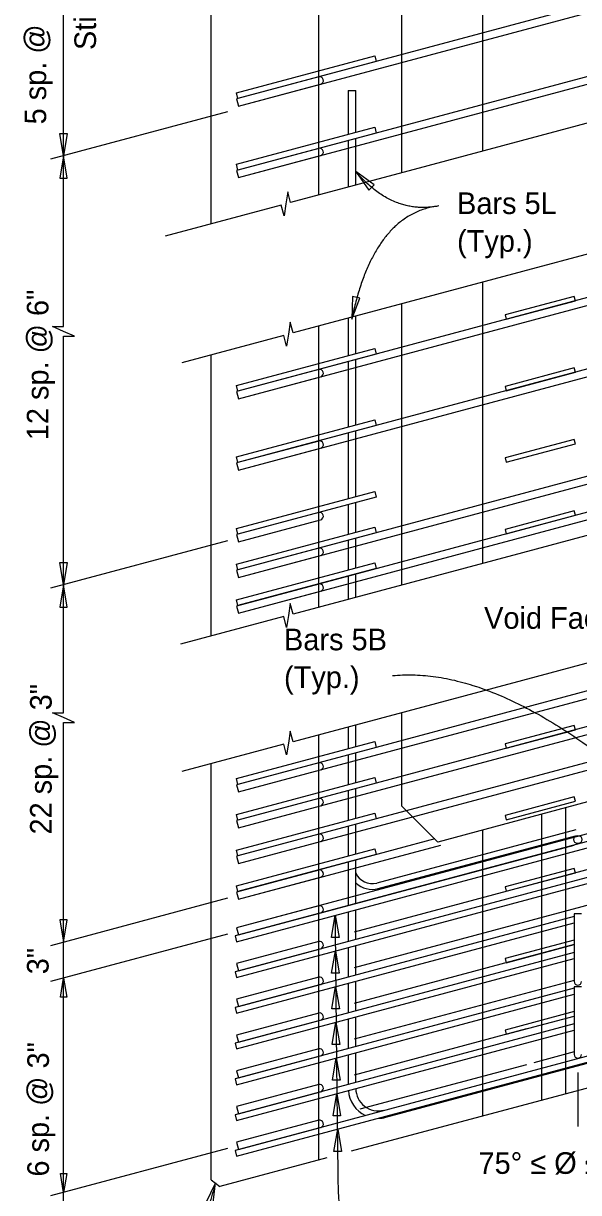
# Model space of a CAD drawing. Extents: x 0 to 30.8, y 0 to 19.8.
# Drawn here: x 19.16 to 23.04, y 4.26 to 12.43 of the extents above; entities that cross this region are included whole.
import ezdxf

# ---------------------------------------------------------------- set-up
doc = ezdxf.new("R2010")
doc.units = 0
for name, color, linetype in [('BeamConc', 7, 'Continuous'), ('BeamConc_h', 7, 'Continuous'), ('Dimension', 7, 'Continuous'), ('Miscellaneous', 7, 'Continuous'), ('Rebar', 7, 'Continuous'), ('Rebar_h', 7, 'Continuous'), ('TextStructures', 7, 'Continuous')]:
    doc.layers.add(name, color=color, linetype=linetype)

msp = doc.modelspace()

# ---------------------------------------------------------------- linework, layer by layer
at = {"layer": 'BeamConc'}
for p, q in [((20.4733, 11.0324), (20.4733, 17.3848)), ((21.8066, 11.3895), (21.8066, 17.3848)), ((21.8066, 8.5073), (21.8066, 10.4739)), ((20.4733, 8.1502), (20.4733, 10.1168)), ((26.1307, 7.8017), (22.0566, 6.71)), ((21.8066, 6.96), (21.8066, 7.615)), ((20.4733, 4.3482), (20.4733, 7.2578)), ((22.0566, 6.71), (21.8066, 6.96)), ((28.8712, 6.536), (21.4512, 4.5478)), ((21.2812, 4.5022), (20.5336, 4.3019)), ((20.4733, 4.3482), (20.5336, 4.3019))]:
    msp.add_line(p, q, dxfattribs=at)
at = {"layer": 'BeamConc_h'}
for p, q in [((22.3691, 17.3848), (22.3691, 11.5403)), ((21.2233, 17.3031), (21.2233, 11.2333)), ((22.3691, 10.6246), (22.3691, 8.658)), ((21.2232, 10.3177), (21.2232, 8.3511)), ((21.2232, 7.4587), (21.2232, 4.4867)), ((22.3691, 6.7937), (22.3691, 4.7937))]:
    msp.add_line(p, q, dxfattribs=at)
at = {"layer": 'Dimension'}
for p, q in [((20.5878, 11.8165), (19.3501, 11.4848)), ((20.5878, 8.8164), (19.3501, 8.4848)), ((20.5878, 6.3164), (19.3501, 5.9848)), ((20.5878, 6.0664), (19.3501, 5.7348)), ((23.0357, 5.0977), (23.0357, 4.7216)), ((20.5878, 4.5664), (19.3501, 4.2348))]:
    msp.add_line(p, q, dxfattribs=at)
for points in [[(19.4418, 11.5094), (19.4418, 17.646)], [(24.705, 12.1159), (24.6925, 12.1626), (21.9874, 11.438)], [(26.8097, 11.8141), (24.7349, 11.2583), (24.7149, 11.3331), (24.7024, 11.2496), (24.6897, 11.1659), (24.6697, 11.2408), (22.6484, 10.6994)], [(19.4418, 8.5094), (19.4418, 10.2464), (19.5193, 10.2464), (19.4418, 10.2801), (19.3643, 10.3139), (19.4418, 10.3139), (19.4418, 11.5094)], [(21.9874, 11.438), (21.0281, 11.181), (21.0081, 11.2558), (20.9956, 11.1723), (20.9829, 11.0886), (20.9629, 11.1635), (20.1516, 10.9463)], [(22.6484, 10.6994), (21.0452, 10.27), (21.0252, 10.3448), (21.0127, 10.2613), (21, 10.1776), (20.98, 10.2525), (20.2685, 10.0619)], [(26.8097, 9.8475), (24.7349, 9.2917), (24.7149, 9.3665), (24.7024, 9.283), (24.6897, 9.1993), (24.6697, 9.2742), (22.6484, 8.7328)], [(27.0226, 9.0121), (24.7349, 8.3994), (24.7149, 8.4742), (24.7024, 8.3906), (24.6897, 8.307), (24.6697, 8.3819), (22.6484, 7.8405)], [(22.6484, 8.7328), (21.0452, 8.3034), (21.0252, 8.3782), (21.0127, 8.2946), (21, 8.211), (20.98, 8.2859), (20.2598, 8.093)], [(19.4418, 3.4638), (19.4418, 7.5463), (19.5193, 7.5463), (19.4418, 7.58), (19.3643, 7.6138), (19.4418, 7.6138), (19.4418, 8.5094)], [(22.6484, 7.8405), (21.0452, 7.411), (21.0252, 7.4858), (21.0127, 7.4023), (21, 7.3186), (20.98, 7.3935), (20.2688, 7.203)]]:
    msp.add_lwpolyline(points, dxfattribs=at)
for points in [[(19.4418, 11.5094), (19.4153, 11.6656), (19.4682, 11.6656)], [(19.4418, 11.5094), (19.4153, 11.3532), (19.4682, 11.3532)], [(21.4837, 11.399), (21.5742, 11.269), (21.612, 11.3061)], [(21.4553, 10.3665), (21.5132, 10.5139), (21.4614, 10.5248)], [(19.4418, 8.5094), (19.4153, 8.6656), (19.4682, 8.6656)], [(19.4418, 8.5094), (19.4153, 8.3532), (19.4682, 8.3532)], [(19.4418, 6.0094), (19.4682, 6.1656), (19.4153, 6.1656)], [(21.3409, 6.1981), (21.3673, 6.0419), (21.3144, 6.0419)], [(21.3418, 5.9483), (21.3682, 5.7921), (21.3153, 5.7921)], [(19.4418, 5.7591), (19.4639, 5.6254), (19.4197, 5.6254)], [(21.343, 5.6987), (21.3695, 5.5425), (21.3166, 5.5425)], [(21.345, 5.4492), (21.3715, 5.293), (21.3186, 5.293)], [(21.3477, 5.1999), (21.3742, 5.0437), (21.3213, 5.0437)], [(21.3516, 4.9509), (21.378, 4.7948), (21.3251, 4.7948)], [(21.3576, 4.7026), (21.3841, 4.5464), (21.3312, 4.5464)], [(19.4418, 4.2591), (19.4197, 4.3929), (19.4639, 4.3929)], [(20.5025, 4.3265), (20.4348, 4.1833), (20.4858, 4.169)]]:
    msp.add_lwpolyline(points, close=True, dxfattribs=at)
for points in [[(22.065, 11.1583), (21.7425, 11.0939), (21.4837, 11.399)], [(22.065, 11.1583), (21.6095, 11.1031), (21.4553, 10.3665)], [(21.7414, 7.8736), (22.5391, 7.9529), (23.6765, 6.9165)], [(21.7531, 3.8369), (21.4602, 3.8052), (21.3667, 4.1157), (21.3585, 4.4637), (21.3409, 6.1981)], [(20.502, 4.3262), (20.4214, 3.9839), (19.9054, 3.1968), (20.338, 3.1878)]]:
    msp.add_open_spline(points, degree=2, dxfattribs=at)
at = {"layer": 'Miscellaneous'}
for p, q in [((22.7816, 6.9043), (22.7816, 4.9043)), ((22.9483, 6.9489), (22.9483, 4.9489))]:
    msp.add_line(p, q, dxfattribs=at)
at = {"layer": 'Rebar'}
for p, q in [((20.6499, 11.9493), (21.6159, 12.2081)), ((21.6159, 12.2081), (21.6267, 12.1678)), ((21.6267, 12.1678), (20.6607, 11.909)), ((21.2251, 12.0602), (20.6513, 11.9065)), ((20.6607, 11.909), (20.6499, 11.9493)), ((20.6648, 11.8562), (21.2385, 12.0099)), ((21.4316, 11.9644), (21.4316, 11.6587)), ((21.4316, 11.9644), (21.4837, 11.9644)), ((21.4837, 11.6727), (21.4837, 11.9644)), ((20.6513, 11.9065), (20.6648, 11.8562)), ((20.6499, 11.4493), (21.6159, 11.7081)), ((21.6159, 11.7081), (21.6267, 11.6678)), ((21.6267, 11.6678), (20.6607, 11.409)), ((21.4316, 11.6155), (21.4316, 11.2891)), ((21.4837, 11.3031), (21.4837, 11.6295)), ((21.2251, 11.5602), (20.6513, 11.4065)), ((20.6607, 11.409), (20.6499, 11.4493)), ((20.6648, 11.3562), (21.2385, 11.5099)), ((20.6513, 11.4065), (20.6648, 11.3562)), ((21.4837, 10.1266), (21.4837, 10.3875)), ((21.4316, 10.3735), (21.4316, 10.1127)), ((20.6499, 9.9032), (21.6159, 10.1621)), ((21.6159, 10.1621), (21.6267, 10.1218)), ((21.6267, 10.1218), (20.6607, 9.863)), ((21.4316, 10.0695), (21.4316, 9.6127)), ((21.4837, 9.6266), (21.4837, 10.0835)), ((21.225, 10.0141), (20.6513, 9.8604)), ((20.6607, 9.863), (20.6499, 9.9032)), ((20.6648, 9.8101), (21.2385, 9.9638)), ((20.6513, 9.8604), (20.6648, 9.8101)), ((20.6499, 9.4032), (21.6159, 9.6621)), ((21.6159, 9.6621), (21.6267, 9.6218)), ((21.6267, 9.6218), (20.6607, 9.363)), ((21.4316, 9.5695), (21.4316, 9.1127)), ((21.4837, 9.1266), (21.4837, 9.5835)), ((21.225, 9.5141), (20.6513, 9.3604)), ((20.6607, 9.363), (20.6499, 9.4032)), ((20.6648, 9.3101), (21.2385, 9.4638)), ((20.6513, 9.3604), (20.6648, 9.3101)), ((20.6499, 8.9032), (21.6159, 9.1621)), ((21.6159, 9.1621), (21.6267, 9.1218)), ((21.6267, 9.1218), (20.6607, 8.863)), ((21.4837, 8.8766), (21.4837, 9.0835)), ((21.225, 9.0141), (20.6513, 8.8604)), ((21.4316, 9.0695), (21.4316, 8.8627)), ((20.6499, 8.6532), (21.6159, 8.9121)), ((20.6648, 8.8101), (21.2385, 8.9638)), ((21.6159, 8.9121), (21.6267, 8.8718)), ((20.6607, 8.863), (20.6499, 8.9032)), ((20.6513, 8.8604), (20.6648, 8.8101)), ((21.6267, 8.8718), (20.6607, 8.613)), ((21.4837, 8.6266), (21.4837, 8.8335)), ((21.225, 8.7641), (20.6513, 8.6104)), ((21.4316, 8.8195), (21.4316, 8.6127)), ((20.6648, 8.5601), (21.2385, 8.7138)), ((20.6499, 8.4032), (21.6159, 8.6621)), ((20.6607, 8.613), (20.6499, 8.6532)), ((20.6513, 8.6104), (20.6648, 8.5601)), ((21.6267, 8.6218), (20.6607, 8.363)), ((21.6159, 8.6621), (21.6267, 8.6218)), ((21.225, 8.5141), (20.6513, 8.3604)), ((21.4316, 8.5695), (21.4316, 8.4069)), ((21.4837, 8.4208), (21.4837, 8.5835)), ((20.6648, 8.3101), (21.2385, 8.4638)), ((20.6607, 8.363), (20.6499, 8.4032)), ((20.6513, 8.3604), (20.6648, 8.3101)), ((28.7541, 7.9776), (20.6399, 5.8034)), ((20.6507, 5.7632), (28.7649, 7.9374)), ((27.2958, 7.8369), (20.6399, 6.0534)), ((20.6507, 6.0132), (27.3031, 7.7957)), ((21.4837, 7.3766), (21.4837, 7.5285)), ((21.4316, 7.5145), (21.4316, 7.3627)), ((20.6499, 7.1532), (21.6159, 7.4121)), ((21.6267, 7.3718), (20.6607, 7.113)), ((21.6159, 7.4121), (21.6267, 7.3718)), ((21.4316, 7.3195), (21.4316, 7.1127)), ((21.4837, 7.1266), (21.4837, 7.3335)), ((21.225, 7.2641), (20.6513, 7.1104)), ((20.6648, 7.0601), (21.2385, 7.2138)), ((20.6499, 6.9032), (21.6159, 7.1621)), ((20.6607, 7.113), (20.6499, 7.1532)), ((21.6267, 7.1218), (20.6607, 6.863)), ((21.6159, 7.1621), (21.6267, 7.1218)), ((20.6513, 7.1104), (20.6648, 7.0601)), ((21.4316, 7.0695), (21.4316, 6.8627)), ((21.4837, 6.8766), (21.4837, 7.0834)), ((21.225, 7.0141), (20.6513, 6.8604)), ((20.6648, 6.8101), (21.2385, 6.9638)), ((20.6499, 6.6532), (21.6159, 6.9121)), ((20.6607, 6.863), (20.6499, 6.9032)), ((21.6267, 6.8718), (20.6607, 6.613)), ((21.6159, 6.9121), (21.6267, 6.8718)), ((20.6513, 6.8604), (20.6648, 6.8101)), ((21.4316, 6.8195), (21.4316, 6.6127)), ((21.4837, 6.6266), (21.4837, 6.8334)), ((23.0224, 6.7962), (21.6306, 6.4233)), ((21.225, 6.7641), (20.6513, 6.6104)), ((20.6648, 6.5601), (21.2385, 6.7138)), ((21.6414, 6.3845), (23.0203, 6.754)), ((20.6499, 6.4032), (21.6159, 6.6621)), ((20.6607, 6.613), (20.6499, 6.6532)), ((21.6159, 6.6621), (21.6267, 6.6218)), ((20.6513, 6.6104), (20.6648, 6.5601)), ((21.6267, 6.6218), (20.6607, 6.363)), ((21.4316, 6.5695), (21.4316, 6.2655)), ((21.4837, 6.2795), (21.4837, 6.5835)), ((21.225, 6.5141), (20.6513, 6.3604)), ((20.6648, 6.3101), (21.2385, 6.4638)), ((27.5855, 6.4145), (20.6399, 4.5534)), ((20.6607, 6.363), (20.6499, 6.4032)), ((21.6938, 4.7854), (27.8189, 6.4266)), ((20.6507, 4.5132), (27.598, 6.3747)), ((20.6513, 6.3604), (20.6648, 6.3101)), ((21.225, 6.2641), (20.6513, 6.1104)), ((21.4316, 6.2224), (21.4316, 6.0155)), ((21.4837, 6.0295), (21.4837, 6.2364)), ((23.0097, 6.1884), (20.6399, 5.5534)), ((20.6507, 5.5132), (23.0097, 6.1453)), ((20.6648, 6.0601), (21.2385, 6.2138)), ((23.0097, 6.2084), (23.0097, 5.7344)), ((23.0618, 6.2084), (23.0097, 6.2084)), ((20.6399, 6.0534), (20.6507, 6.0132)), ((20.6513, 6.1104), (20.6648, 6.0601)), ((21.225, 6.0141), (20.6513, 5.8604)), ((21.4316, 5.9724), (21.4316, 5.7655)), ((21.4837, 5.7795), (21.4837, 5.9864)), ((23.0097, 5.9384), (20.6399, 5.3034)), ((20.6507, 5.2632), (23.0097, 5.8953)), ((20.6648, 5.8101), (21.2385, 5.9638)), ((20.6513, 5.8604), (20.6648, 5.8101)), ((20.6399, 5.8034), (20.6507, 5.7632)), ((21.225, 5.7641), (20.6513, 5.6104)), ((21.4837, 5.5295), (21.4837, 5.7364)), ((23.0097, 5.6884), (20.6399, 5.0534)), ((20.6507, 5.0132), (23.0097, 5.6453)), ((20.6648, 5.5601), (21.2385, 5.7138)), ((21.4316, 5.7224), (21.4316, 5.5155)), ((23.0097, 5.6984), (23.0097, 5.2244)), ((23.0618, 5.6984), (23.0097, 5.6984)), ((20.6513, 5.6104), (20.6648, 5.5601)), ((20.6399, 5.5534), (20.6507, 5.5132)), ((21.225, 5.5141), (20.6513, 5.3604)), ((21.4837, 5.2796), (21.4837, 5.4864)), ((23.0097, 5.4384), (20.6399, 4.8034)), ((20.6648, 5.3101), (21.2385, 5.4638)), ((21.4316, 5.4724), (21.4316, 5.2656)), ((20.6507, 4.7632), (23.0097, 5.3953)), ((20.6513, 5.3604), (20.6648, 5.3101)), ((20.6399, 5.3034), (20.6507, 5.2632)), ((21.225, 5.2641), (20.6513, 5.1104)), ((21.4837, 5.0295), (21.4837, 5.2364)), ((20.6648, 5.0601), (21.2385, 5.2138)), ((21.4316, 5.2224), (21.4316, 5.0155)), ((20.6513, 5.1104), (20.6648, 5.0601)), ((20.6399, 5.0534), (20.6507, 5.0132)), ((21.225, 5.0141), (20.6513, 4.8604)), ((20.6648, 4.8101), (21.2385, 4.9638)), ((20.6513, 4.8604), (20.6648, 4.8101)), ((20.6399, 4.8034), (20.6507, 4.7632)), ((21.225, 4.7641), (20.6513, 4.6104)), ((20.6648, 4.5601), (21.2385, 4.7138)), ((20.6513, 4.6104), (20.6648, 4.5601)), ((20.6399, 4.5534), (20.6507, 4.5132))]:
    msp.add_line(p, q, dxfattribs=at)
for points in [[(22.5357, 10.3653), (23.0187, 10.4947), (23.0106, 10.5249), (22.5277, 10.3955)], [(22.5357, 9.8653), (23.0187, 9.9947), (23.0106, 10.0249), (22.5277, 9.8955)], [(22.5357, 9.3653), (23.0187, 9.4947), (23.0106, 9.5249), (22.5277, 9.3955)], [(22.5357, 8.8653), (23.0187, 8.9947), (23.0106, 9.0249), (22.5277, 8.8955)], [(22.5357, 7.3653), (23.0187, 7.4947), (23.0106, 7.5249), (22.5277, 7.3955)], [(22.5357, 6.8653), (23.0187, 6.9947), (23.0106, 7.0249), (22.5277, 6.8955)], [(22.5357, 6.3653), (23.0187, 6.4947), (23.0106, 6.5249), (22.5277, 6.3955)]]:
    msp.add_lwpolyline(points, close=True, dxfattribs=at)
for points in [[(23.0097, 6.0247), (22.5277, 5.8955), (22.5357, 5.8653), (23.0097, 5.9923)], [(23.0097, 5.5247), (22.5277, 5.3955), (22.5357, 5.3653), (23.0097, 5.4923)]]:
    msp.add_lwpolyline(points, dxfattribs=at)
msp.add_circle((23.0357, 6.7274), 0.0287, dxfattribs=at)
for centre, radius, start, end in [((21.2318, 12.0351), 0.026, 285, 105), ((21.2318, 11.5351), 0.026, 285, 105), ((21.2318, 9.989), 0.026, 285, 105), ((21.2318, 9.489), 0.026, 285, 105), ((21.2318, 8.989), 0.026, 285, 105), ((21.2318, 8.739), 0.026, 285, 105), ((21.2318, 8.489), 0.026, 285, 105), ((21.2318, 7.239), 0.026, 285, 105), ((21.2318, 6.989), 0.026, 285, 105), ((21.2318, 6.739), 0.026, 285, 105), ((21.2318, 6.489), 0.026, 285, 105), ((21.5983, 6.544), 0.125, 203.55647, 285), ((21.5983, 6.5455), 0.1667, 226.56254, 285), ((21.2318, 6.239), 0.026, 285, 105), ((21.2318, 5.989), 0.026, 285, 105), ((21.2318, 5.739), 0.026, 285, 105), ((23.0357, 5.7344), 0.026, 179.99982, 359.99949), ((21.2318, 5.489), 0.026, 285, 105), ((21.2318, 5.239), 0.026, 285, 105), ((23.0357, 5.2244), 0.026, 179.99982, 359.99949), ((21.2318, 4.989), 0.026, 285, 105), ((21.6399, 4.9866), 0.2083, 183.86653, 245.0097), ((21.6399, 4.9866), 0.1562, 180, 285), ((21.2318, 4.739), 0.026, 285, 105), ((21.6399, 4.9866), 0.2083, 270.06109, 285)]:
    msp.add_arc(centre, radius, start, end, dxfattribs=at)
at = {"layer": 'Rebar_h'}
for p, q in [((21.2385, 7.2139), (27.0661, 8.7754)), ((27.0527, 8.8256), (21.6267, 7.3717)), ((27.1152, 8.5924), (21.6267, 7.1217)), ((21.2385, 6.9639), (27.1286, 8.5421)), ((27.1777, 8.3591), (21.6267, 6.8717)), ((21.2385, 6.7139), (27.1911, 8.3089)), ((27.2888, 7.8889), (20.6513, 6.1104)), ((20.6513, 6.8604), (20.6648, 6.8101)), ((22.0353, 6.7312), (20.6513, 6.3604)), ((20.6648, 6.3101), (22.0778, 6.6888)), ((20.6648, 6.0601), (23.0097, 6.6885)), ((20.6513, 6.6104), (20.6648, 6.5601)), ((20.6513, 6.3604), (20.6648, 6.3101)), ((20.6513, 6.1104), (20.6648, 6.0601)), ((23.0097, 5.2423), (22.7284, 5.167)), ((22.6764, 5.153), (21.5115, 4.8409)), ((20.6513, 4.6104), (20.6648, 4.5601))]:
    msp.add_line(p, q, dxfattribs=at)
for points in [[(28.7407, 14.074), (20.6513, 11.9064), (20.6648, 11.8562), (28.7541, 14.0237)], [(28.7407, 13.5739), (20.6513, 11.4064), (20.6648, 11.3562), (28.7541, 13.5237)], [(28.7302, 12.0251), (20.6513, 9.8604), (20.6648, 9.8101), (28.7437, 11.9749)], [(28.7302, 11.5251), (20.6513, 9.3604), (20.6648, 9.3101), (28.7437, 11.4749)], [(28.7302, 10.7751), (20.6513, 8.6104), (20.6648, 8.5601), (28.7437, 10.7249)], [(28.7302, 10.5251), (20.6513, 8.3604), (20.6648, 8.3101), (28.7437, 10.4749)]]:
    msp.add_lwpolyline(points, close=True, dxfattribs=at)
for points in [[(27.9316, 7.8111), (21.4733, 6.0806)], [(27.9316, 7.5611), (21.4733, 5.8306)], [(23.0097, 5.9923), (21.4733, 5.5806)], [(23.0097, 5.7423), (21.4733, 5.3306)], [(22.6764, 5.403), (21.4733, 5.0806)]]:
    msp.add_lwpolyline(points, dxfattribs=at)

# ---------------------------------------------------------------- texts
at = {"layer": 'Dimension'}
for s, p in [('Bars 5L', (22.1917, 11.1014)), ('(Typ.)', (22.1917, 10.8374)), ('Bars 5B', (20.9825, 8.0508)), ('(Typ.)', (20.9825, 7.7868))]:
    msp.add_text(s, height=0.1512, dxfattribs=at).set_placement(p)
at = {"layer": 'TextStructures'}
for s, p in [('5 sp. @ 6" (along ℄ of Beam)', (19.3205, 11.7282)), ('Stirrup Transition Zone ', (19.6689, 12.2481)), ('12 sp. @ 6" ', (19.3363, 9.5199)), ('22 sp. @ 3"', (19.3588, 6.7626)), ('3"', (19.3374, 5.7854)), ('6 sp. @ 3"', (19.3397, 4.3706))]:
    msp.add_text(s, height=0.1512, rotation=90, dxfattribs=at).set_placement(p)
for s, p in [('Void Face', (22.3808, 8.2013)), ('75° ≤ Ø ≤ 90°', (22.3415, 4.3895))]:
    msp.add_text(s, height=0.1512, dxfattribs=at).set_placement(p)

doc.saveas('drawing.dxf')
